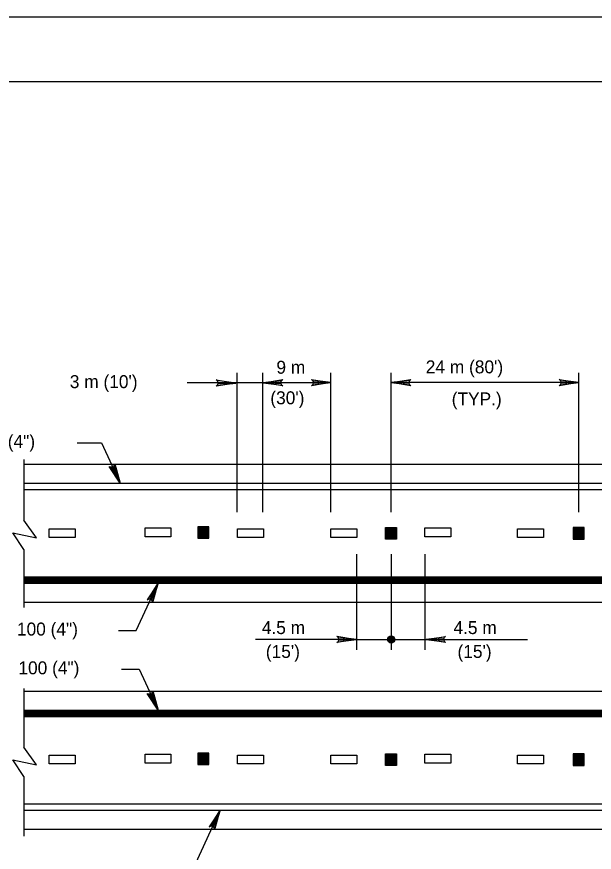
# Model space of a CAD drawing. Extents: x 639362 to 641108, y 298458 to 299646.
# Drawn here: x 639841.8 to 639975.6, y 299452 to 299645.6 of the extents above; entities that cross this region are included whole.
import ezdxf

# ---------------------------------------------------------------- set-up
doc = ezdxf.new("R2010")
doc.units = 0
for name, color, linetype in [('1', 7, 'Continuous'), ('2', 7, 'Continuous'), ('PLT-BNDY', 7, 'Continuous')]:
    doc.layers.add(name, color=color, linetype=linetype)

msp = doc.modelspace()

# ---------------------------------------------------------------- linework, layer by layer
at = {"layer": '1'}
msp.add_line((639402.31, 299630.63), (640188.31, 299630.63), dxfattribs=at)
at = {"layer": '2'}
for p, q in [((639892.84, 299530.81), (639892.84, 299563.14)), ((639898.78, 299530.81), (639898.78, 299563.14)), ((639914.6, 299530.81), (639914.6, 299563.14)), ((639928.56, 299530.81), (639928.56, 299563.14)), ((639972, 299530.81), (639972, 299563.14)), ((639881.3, 299560.84), (639898.78, 299560.84)), ((639898.78, 299560.84), (639914.6, 299560.84)), ((639972, 299560.84), (639928.56, 299560.84)), ((639855.77, 299546.87), (639861.45, 299546.87)), ((639861.45, 299546.87), (639865.76, 299537.58)), ((639843.44, 299543.05), (639843.44, 299529.01)), ((639843.44, 299541.93), (640077.95, 299541.93)), ((639843.44, 299537.58), (640077.95, 299537.58)), ((639843.44, 299536.08), (640077.95, 299536.08)), ((639846.39, 299524.88), (639843.44, 299529.01)), ((639849.33, 299524.93), (639849.33, 299527)), ((639849.33, 299527), (639855.34, 299527)), ((639855.34, 299527), (639855.34, 299524.93)), ((639871.52, 299525.12), (639871.52, 299527.19)), ((639871.52, 299527.19), (639877.53, 299527.19)), ((639877.53, 299527.19), (639877.53, 299525.12)), ((639886.28, 299527.42), (639883.78, 299527.42)), ((639883.78, 299527.42), (639883.78, 299524.77)), ((639886.09, 299527.29), (639883.96, 299527.29)), ((639883.96, 299527.29), (639883.96, 299524.89)), ((639885.91, 299527.11), (639884.14, 299527.11)), ((639884.14, 299527.11), (639884.14, 299525.07)), ((639885.73, 299526.93), (639884.32, 299526.93)), ((639884.32, 299526.93), (639884.32, 299525.25)), ((639885.56, 299526.76), (639884.49, 299526.76)), ((639884.49, 299526.76), (639884.49, 299525.43)), ((639884.67, 299526.58), (639884.67, 299525.6)), ((639885.38, 299526.58), (639884.67, 299526.58)), ((639885.2, 299526.4), (639884.85, 299526.4)), ((639884.85, 299526.4), (639884.85, 299525.78)), ((639885.2, 299525.78), (639885.2, 299526.4)), ((639885.38, 299525.6), (639885.38, 299526.58)), ((639885.56, 299525.43), (639885.56, 299526.76)), ((639885.73, 299525.25), (639885.73, 299526.93)), ((639885.91, 299525.07), (639885.91, 299527.11)), ((639886.09, 299524.89), (639886.09, 299527.29)), ((639886.28, 299524.77), (639886.28, 299527.42)), ((639892.97, 299524.93), (639892.97, 299527)), ((639892.97, 299527), (639898.98, 299527)), ((639898.98, 299527), (639898.98, 299524.93)), ((639914.6, 299524.93), (639914.6, 299527)), ((639914.6, 299527), (639920.61, 299527)), ((639920.61, 299527), (639920.61, 299524.93)), ((639927.27, 299527.26), (639929.77, 299527.26)), ((639927.27, 299524.6), (639927.27, 299527.26)), ((639927.46, 299527.13), (639929.58, 299527.13)), ((639927.46, 299524.73), (639927.46, 299527.13)), ((639927.64, 299526.95), (639929.41, 299526.95)), ((639927.64, 299524.91), (639927.64, 299526.95)), ((639927.81, 299526.77), (639929.23, 299526.77)), ((639927.81, 299525.08), (639927.81, 299526.77)), ((639927.99, 299526.59), (639929.05, 299526.59)), ((639927.99, 299525.26), (639927.99, 299526.59)), ((639928.16, 299525.44), (639928.16, 299526.42)), ((639928.16, 299526.42), (639928.88, 299526.42)), ((639928.88, 299526.42), (639928.88, 299525.44)), ((639929.05, 299526.59), (639929.05, 299525.26)), ((639929.23, 299526.77), (639929.23, 299525.08)), ((639929.41, 299526.95), (639929.41, 299524.91)), ((639929.58, 299527.13), (639929.58, 299524.73)), ((639929.77, 299527.26), (639929.77, 299524.6)), ((639936.38, 299525.12), (639936.38, 299527.19)), ((639936.38, 299527.19), (639942.39, 299527.19)), ((639942.39, 299527.19), (639942.39, 299525.12)), ((639957.83, 299524.93), (639957.83, 299527)), ((639957.83, 299527), (639963.85, 299527)), ((639963.85, 299527), (639963.85, 299524.93)), ((639973.23, 299527.26), (639970.74, 299527.26)), ((639970.74, 299527.26), (639970.74, 299524.6)), ((639973.05, 299527.13), (639970.92, 299527.13)), ((639970.92, 299527.13), (639970.92, 299524.73)), ((639972.87, 299526.95), (639971.1, 299526.95)), ((639971.1, 299526.95), (639971.1, 299524.91)), ((639972.69, 299526.77), (639971.27, 299526.77)), ((639971.27, 299526.77), (639971.27, 299525.08)), ((639972.52, 299526.59), (639971.45, 299526.59)), ((639971.45, 299526.59), (639971.45, 299525.26)), ((639971.63, 299526.42), (639971.63, 299525.44)), ((639972.34, 299526.42), (639971.63, 299526.42)), ((639972.34, 299525.44), (639972.34, 299526.42)), ((639972.52, 299525.26), (639972.52, 299526.59)), ((639972.69, 299525.08), (639972.69, 299526.77)), ((639972.87, 299524.91), (639972.87, 299526.95)), ((639973.05, 299524.73), (639973.05, 299527.13)), ((639973.23, 299524.6), (639973.23, 299527.26)), ((639843.44, 299522.15), (639840.87, 299526.02)), ((639840.87, 299526.02), (639846.39, 299524.88)), ((639855.34, 299524.93), (639849.33, 299524.93)), ((639877.53, 299525.12), (639871.52, 299525.12)), ((639883.78, 299524.77), (639886.28, 299524.77)), ((639883.96, 299524.89), (639886.09, 299524.89)), ((639884.14, 299525.07), (639885.91, 299525.07)), ((639884.32, 299525.25), (639885.73, 299525.25)), ((639884.49, 299525.43), (639885.56, 299525.43)), ((639884.67, 299525.6), (639885.38, 299525.6)), ((639884.85, 299525.78), (639885.2, 299525.78)), ((639885.03, 299526.23), (639885.03, 299525.96)), ((639898.98, 299524.93), (639892.97, 299524.93)), ((639920.61, 299524.93), (639914.6, 299524.93)), ((639929.77, 299524.6), (639927.27, 299524.6)), ((639929.58, 299524.73), (639927.46, 299524.73)), ((639929.41, 299524.91), (639927.64, 299524.91)), ((639929.23, 299525.08), (639927.81, 299525.08)), ((639929.05, 299525.26), (639927.99, 299525.26)), ((639928.88, 299525.44), (639928.16, 299525.44)), ((639928.34, 299526.24), (639928.7, 299526.24)), ((639928.34, 299525.62), (639928.34, 299526.24)), ((639928.7, 299525.62), (639928.34, 299525.62)), ((639928.52, 299526.06), (639928.52, 299525.8)), ((639928.7, 299526.24), (639928.7, 299525.62)), ((639942.39, 299525.12), (639936.38, 299525.12)), ((639963.85, 299524.93), (639957.83, 299524.93)), ((639970.74, 299524.6), (639973.23, 299524.6)), ((639970.92, 299524.73), (639973.05, 299524.73)), ((639971.1, 299524.91), (639972.87, 299524.91)), ((639971.27, 299525.08), (639972.69, 299525.08)), ((639971.45, 299525.26), (639972.52, 299525.26)), ((639971.63, 299525.44), (639972.34, 299525.44)), ((639972.16, 299526.24), (639971.81, 299526.24)), ((639971.81, 299526.24), (639971.81, 299525.62)), ((639971.81, 299525.62), (639972.16, 299525.62)), ((639971.99, 299526.06), (639971.99, 299525.8)), ((639972.16, 299525.62), (639972.16, 299526.24)), ((639843.44, 299522.15), (639843.44, 299508.71)), ((639920.53, 299521.12), (639920.53, 299498.96)), ((639928.56, 299521.12), (639928.56, 299498.96)), ((639936.35, 299521.12), (639936.35, 299498.96)), ((639843.44, 299515.85), (640077.95, 299515.85)), ((639843.44, 299515.7), (640077.95, 299515.7)), ((639843.44, 299515.55), (640077.95, 299515.55)), ((639843.44, 299515.4), (640077.95, 299515.4)), ((639843.44, 299515.25), (640077.95, 299515.25)), ((639843.44, 299515.1), (640077.95, 299515.1)), ((639843.44, 299514.95), (640077.95, 299514.95)), ((639843.44, 299514.8), (640077.95, 299514.8)), ((639843.44, 299514.65), (640077.95, 299514.65)), ((639843.44, 299514.5), (640077.95, 299514.5)), ((639843.44, 299514.35), (640077.95, 299514.35)), ((639869.45, 299503.37), (639874.55, 299514.35)), ((639843.44, 299510), (640077.95, 299510)), ((639865.41, 299503.37), (639869.45, 299503.37)), ((639920.53, 299501.33), (639897.09, 299501.33)), ((639920.53, 299501.33), (639936.35, 299501.33)), ((639936.59, 299501.33), (639960.15, 299501.33)), ((639866.04, 299494.48), (639870.18, 299494.48)), ((639870.18, 299494.48), (639874.58, 299484.98)), ((639843.44, 299489.99), (639843.44, 299476.41)), ((639843.44, 299489.33), (640077.95, 299489.33)), ((639843.44, 299484.98), (640077.95, 299484.98)), ((639843.44, 299484.83), (640077.95, 299484.83)), ((639843.44, 299484.68), (640077.95, 299484.68)), ((639843.44, 299484.53), (640077.95, 299484.53)), ((639843.44, 299484.38), (640077.95, 299484.38)), ((639843.44, 299484.23), (640077.95, 299484.23)), ((639843.44, 299484.08), (640077.95, 299484.08)), ((639843.44, 299483.93), (640077.95, 299483.93)), ((639843.44, 299483.78), (640077.95, 299483.78)), ((639843.44, 299483.63), (640077.95, 299483.63)), ((639843.44, 299483.48), (640077.95, 299483.48)), ((639846.39, 299472.28), (639843.44, 299476.41)), ((639849.33, 299472.49), (639849.33, 299474.55)), ((639849.33, 299474.55), (639855.34, 299474.55)), ((639855.34, 299474.55), (639855.34, 299472.49)), ((639871.52, 299472.68), (639871.52, 299474.74)), ((639871.52, 299474.74), (639877.53, 299474.74)), ((639877.53, 299474.74), (639877.53, 299472.68)), ((639886.28, 299474.98), (639883.78, 299474.98)), ((639883.78, 299474.98), (639883.78, 299472.32)), ((639886.09, 299474.84), (639883.96, 299474.84)), ((639883.96, 299474.84), (639883.96, 299472.45)), ((639885.91, 299474.67), (639884.14, 299474.67)), ((639884.14, 299474.67), (639884.14, 299472.63)), ((639885.73, 299474.49), (639884.32, 299474.49)), ((639884.32, 299474.49), (639884.32, 299472.8)), ((639885.56, 299474.31), (639884.49, 299474.31)), ((639884.49, 299474.31), (639884.49, 299472.98)), ((639884.67, 299474.13), (639884.67, 299473.16)), ((639885.38, 299474.13), (639884.67, 299474.13)), ((639885.38, 299473.16), (639885.38, 299474.13)), ((639885.56, 299472.98), (639885.56, 299474.31)), ((639885.73, 299472.8), (639885.73, 299474.49)), ((639885.91, 299472.63), (639885.91, 299474.67)), ((639886.09, 299472.45), (639886.09, 299474.84)), ((639886.28, 299472.32), (639886.28, 299474.98)), ((639892.97, 299472.49), (639892.97, 299474.55)), ((639892.97, 299474.55), (639898.98, 299474.55)), ((639898.98, 299474.55), (639898.98, 299472.49)), ((639914.6, 299472.49), (639914.6, 299474.55)), ((639914.6, 299474.55), (639920.61, 299474.55)), ((639920.61, 299474.55), (639920.61, 299472.49)), ((639927.27, 299474.81), (639929.77, 299474.81)), ((639927.27, 299472.16), (639927.27, 299474.81)), ((639927.46, 299474.68), (639929.58, 299474.68)), ((639927.46, 299472.29), (639927.46, 299474.68)), ((639927.64, 299474.5), (639929.41, 299474.5)), ((639927.64, 299472.47), (639927.64, 299474.5)), ((639927.81, 299474.33), (639929.23, 299474.33)), ((639927.81, 299472.64), (639927.81, 299474.33)), ((639927.99, 299474.15), (639929.05, 299474.15)), ((639927.99, 299472.82), (639927.99, 299474.15)), ((639929.05, 299474.15), (639929.05, 299472.82)), ((639929.23, 299474.33), (639929.23, 299472.64)), ((639929.41, 299474.5), (639929.41, 299472.47)), ((639929.58, 299474.68), (639929.58, 299472.29)), ((639929.77, 299474.81), (639929.77, 299472.16)), ((639936.38, 299472.68), (639936.38, 299474.74)), ((639936.38, 299474.74), (639942.39, 299474.74)), ((639942.39, 299474.74), (639942.39, 299472.68)), ((639957.83, 299472.49), (639957.83, 299474.55)), ((639957.83, 299474.55), (639963.85, 299474.55)), ((639963.85, 299474.55), (639963.85, 299472.49)), ((639973.23, 299474.81), (639970.74, 299474.81)), ((639970.74, 299474.81), (639970.74, 299472.16)), ((639973.05, 299474.68), (639970.92, 299474.68)), ((639970.92, 299474.68), (639970.92, 299472.29)), ((639972.87, 299474.5), (639971.1, 299474.5)), ((639971.1, 299474.5), (639971.1, 299472.47)), ((639972.69, 299474.33), (639971.27, 299474.33)), ((639971.27, 299474.33), (639971.27, 299472.64)), ((639972.52, 299474.15), (639971.45, 299474.15)), ((639971.45, 299474.15), (639971.45, 299472.82)), ((639972.52, 299472.82), (639972.52, 299474.15)), ((639972.69, 299472.64), (639972.69, 299474.33)), ((639972.87, 299472.47), (639972.87, 299474.5)), ((639973.05, 299472.29), (639973.05, 299474.68)), ((639973.23, 299472.16), (639973.23, 299474.81)), ((639843.44, 299469.54), (639840.87, 299473.41)), ((639840.87, 299473.41), (639846.39, 299472.28)), ((639855.34, 299472.49), (639849.33, 299472.49)), ((639877.53, 299472.68), (639871.52, 299472.68)), ((639883.78, 299472.32), (639886.28, 299472.32)), ((639883.96, 299472.45), (639886.09, 299472.45)), ((639884.14, 299472.63), (639885.91, 299472.63)), ((639884.32, 299472.8), (639885.73, 299472.8)), ((639884.49, 299472.98), (639885.56, 299472.98)), ((639884.67, 299473.16), (639885.38, 299473.16)), ((639885.2, 299473.96), (639884.85, 299473.96)), ((639884.85, 299473.96), (639884.85, 299473.34)), ((639884.85, 299473.34), (639885.2, 299473.34)), ((639885.03, 299473.78), (639885.03, 299473.51)), ((639885.2, 299473.34), (639885.2, 299473.96)), ((639898.98, 299472.49), (639892.97, 299472.49)), ((639920.61, 299472.49), (639914.6, 299472.49)), ((639929.77, 299472.16), (639927.27, 299472.16)), ((639929.58, 299472.29), (639927.46, 299472.29)), ((639929.41, 299472.47), (639927.64, 299472.47)), ((639929.23, 299472.64), (639927.81, 299472.64)), ((639929.05, 299472.82), (639927.99, 299472.82)), ((639928.16, 299472.99), (639928.16, 299473.97)), ((639928.16, 299473.97), (639928.88, 299473.97)), ((639928.88, 299472.99), (639928.16, 299472.99)), ((639928.34, 299473.79), (639928.7, 299473.79)), ((639928.34, 299473.17), (639928.34, 299473.79)), ((639928.7, 299473.17), (639928.34, 299473.17)), ((639928.52, 299473.62), (639928.52, 299473.35)), ((639928.7, 299473.79), (639928.7, 299473.17)), ((639928.88, 299473.97), (639928.88, 299472.99)), ((639942.39, 299472.68), (639936.38, 299472.68)), ((639963.85, 299472.49), (639957.83, 299472.49)), ((639970.74, 299472.16), (639973.23, 299472.16)), ((639970.92, 299472.29), (639973.05, 299472.29)), ((639971.1, 299472.47), (639972.87, 299472.47)), ((639971.27, 299472.64), (639972.69, 299472.64)), ((639971.45, 299472.82), (639972.52, 299472.82)), ((639971.63, 299473.97), (639971.63, 299472.99)), ((639972.34, 299473.97), (639971.63, 299473.97)), ((639971.63, 299472.99), (639972.34, 299472.99)), ((639972.16, 299473.79), (639971.81, 299473.79)), ((639971.81, 299473.79), (639971.81, 299473.17)), ((639971.81, 299473.17), (639972.16, 299473.17)), ((639971.99, 299473.62), (639971.99, 299473.35)), ((639972.16, 299473.17), (639972.16, 299473.79)), ((639972.34, 299472.99), (639972.34, 299473.97)), ((639843.44, 299469.54), (639843.44, 299455.72)), ((639843.44, 299463.25), (640077.95, 299463.25)), ((639843.44, 299461.75), (640077.95, 299461.75)), ((639882.43, 299447.68), (639888.96, 299461.75)), ((639843.44, 299457.4), (640077.95, 299457.4))]:
    msp.add_line(p, q, dxfattribs=at)
for points in [[(639888.22, 299561.3), (639888.38, 299560.98), (639892.54, 299560.75), (639888.22, 299561.3), (639888, 299561.49), (639892.54, 299560.75), (639888.39, 299560.55), (639888.23, 299560.24), (639892.54, 299560.75), (639888, 299560.03), (639888.23, 299560.24)], [(639903.19, 299560.27), (639903.03, 299560.58), (639898.87, 299560.81), (639903.19, 299560.27), (639903.41, 299560.08), (639898.87, 299560.81), (639903.02, 299561.02), (639903.18, 299561.33), (639898.87, 299560.81), (639903.41, 299561.53), (639903.18, 299561.33)], [(639910.28, 299561.38), (639910.44, 299561.07), (639914.6, 299560.84), (639910.28, 299561.38), (639910.06, 299561.57), (639914.6, 299560.84), (639910.45, 299560.64), (639910.29, 299560.33), (639914.6, 299560.84), (639910.06, 299560.12), (639910.29, 299560.33)], [(639932.88, 299560.3), (639932.72, 299560.61), (639928.56, 299560.84), (639932.88, 299560.3), (639933.1, 299560.11), (639928.56, 299560.84), (639932.72, 299561.05), (639932.87, 299561.36), (639928.56, 299560.84), (639933.1, 299561.56), (639932.87, 299561.36)], [(639967.68, 299561.38), (639967.84, 299561.07), (639972, 299560.84), (639967.68, 299561.38), (639967.46, 299561.57), (639972, 299560.84), (639967.85, 299560.64), (639967.7, 299560.33), (639972, 299560.84), (639967.46, 299560.12), (639967.7, 299560.33)], [(639864.43, 299541.73), (639864.21, 299541.45), (639865.76, 299537.58), (639864.43, 299541.73), (639864.51, 299542.01), (639865.76, 299537.58), (639863.82, 299541.27), (639863.48, 299541.27), (639865.76, 299537.58), (639863.19, 299541.4), (639863.48, 299541.27)], [(639873.22, 299510.21), (639873, 299510.48), (639874.55, 299514.35), (639873.22, 299510.21), (639873.3, 299509.92), (639874.55, 299514.35), (639872.61, 299510.67), (639872.27, 299510.66), (639874.55, 299514.35), (639871.98, 299510.53), (639872.27, 299510.66)], [(639916.21, 299501.87), (639916.37, 299501.56), (639920.53, 299501.33), (639916.21, 299501.87), (639915.99, 299502.06), (639920.53, 299501.33), (639916.38, 299501.12), (639916.22, 299500.81), (639920.53, 299501.33), (639915.99, 299500.61), (639916.22, 299500.81)], [(639940.95, 299500.78), (639940.79, 299501.1), (639936.64, 299501.33), (639940.95, 299500.78), (639941.17, 299500.59), (639936.64, 299501.33), (639940.79, 299501.53), (639940.94, 299501.84), (639936.64, 299501.33), (639941.17, 299502.05), (639940.94, 299501.84)], [(639873.26, 299489.12), (639873.04, 299488.85), (639874.58, 299484.98), (639873.26, 299489.12), (639873.34, 299489.4), (639874.58, 299484.98), (639872.65, 299488.66), (639872.3, 299488.67), (639874.58, 299484.98), (639872.02, 299488.79), (639872.3, 299488.67)], [(639887.63, 299457.6), (639887.41, 299457.88), (639888.96, 299461.75), (639887.63, 299457.6), (639887.71, 299457.32), (639888.96, 299461.75), (639887.02, 299458.06), (639886.68, 299458.06), (639888.96, 299461.75), (639886.39, 299457.93), (639886.68, 299458.06)]]:
    msp.add_lwpolyline(points, dxfattribs=at)
for radius in [0.817, 0.759, 0.701, 0.643, 0.585, 0.527, 0.469, 0.411, 0.353, 0.295, 0.237, 0.179, 0.121, 0.0627]:
    msp.add_circle((639928.56, 299501.33), radius, dxfattribs=at)
at = {"layer": 'PLT-BNDY'}
msp.add_lwpolyline([(639362.31, 299645.63), (640203.31, 299645.63), (640203.31, 299051.63), (639362.31, 299051.63)], close=True, dxfattribs=at)

# ---------------------------------------------------------------- texts
at = {"layer": '2'}
for s, p in [('9 m', (639901.96, 299562.9)), ("24 m (80')", (639936.56, 299562.99)), ("3 m (10')", (639854.09, 299559.57)), ("(30')", (639900.55, 299555.83)), ('(TYP.)', (639942.57, 299555.57)), ('100 (4")', (639831.91, 299545.73)), ('100 (4")', (639841.84, 299502.24)), ('4.5 m', (639898.57, 299502.58)), ('4.5 m', (639942.98, 299502.58)), ("(15')", (639899.51, 299497.05)), ("(15')", (639943.92, 299497.05)), ('100 (4")', (639842.18, 299493.26))]:
    msp.add_text(s, height=3, dxfattribs=at).set_placement(p)

doc.saveas('drawing.dxf')
